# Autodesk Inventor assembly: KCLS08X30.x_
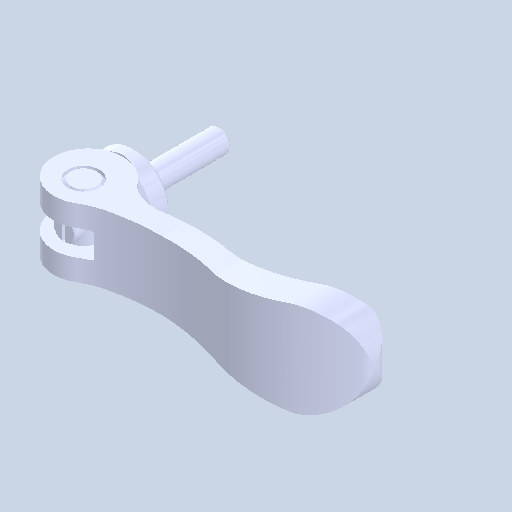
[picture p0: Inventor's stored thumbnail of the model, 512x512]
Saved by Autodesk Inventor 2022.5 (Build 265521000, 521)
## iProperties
Created: 2024-08
Part Number: KCLS08X30.x_
Document SubType Name: Assembly
Designer: ImaoCorp
Author: ImaoCorp
Sending System: SOLIDWORKS 2022-2022290
MC: AMD64
MC_MODEL: Intel64 Family 6 Model 60 Stepping 3, GenuineIntel
OS: Windows_NT
FRU: Parasolid Version 33.1, build 260,  4-25-2022
FORMAT: text
GUISE: transmit
KEY: FILEKCLS08X30.x_t
DATE: Thu Aug 29 10:55:08 2024
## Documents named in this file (5)
- Y:\5.更新分\2024年対応\1001_KCL\データ\kcls08x30\KCLS08X30.x_.iam
- Y:\5.更新分\2024年対応\1001_KCL\データ\kcls08x30\KCLS08X30_01.ipt
- Y:\5.更新分\2024年対応\1001_KCL\データ\kcls08x30\KCLS08X30_02.ipt
- Y:\5.更新分\2024年対応\1001_KCL\データ\kcls08x30\KCLS08X30_03.ipt
- Y:\5.更新分\2024年対応\1001_KCL\データ\kcls08x30\KCLS08X30_04.ipt
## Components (4 placed, 4 different names)
1. KCLS08X30_01
2. KCLS08X30_02
3. KCLS08X30_03
4. KCLS08X30_04
